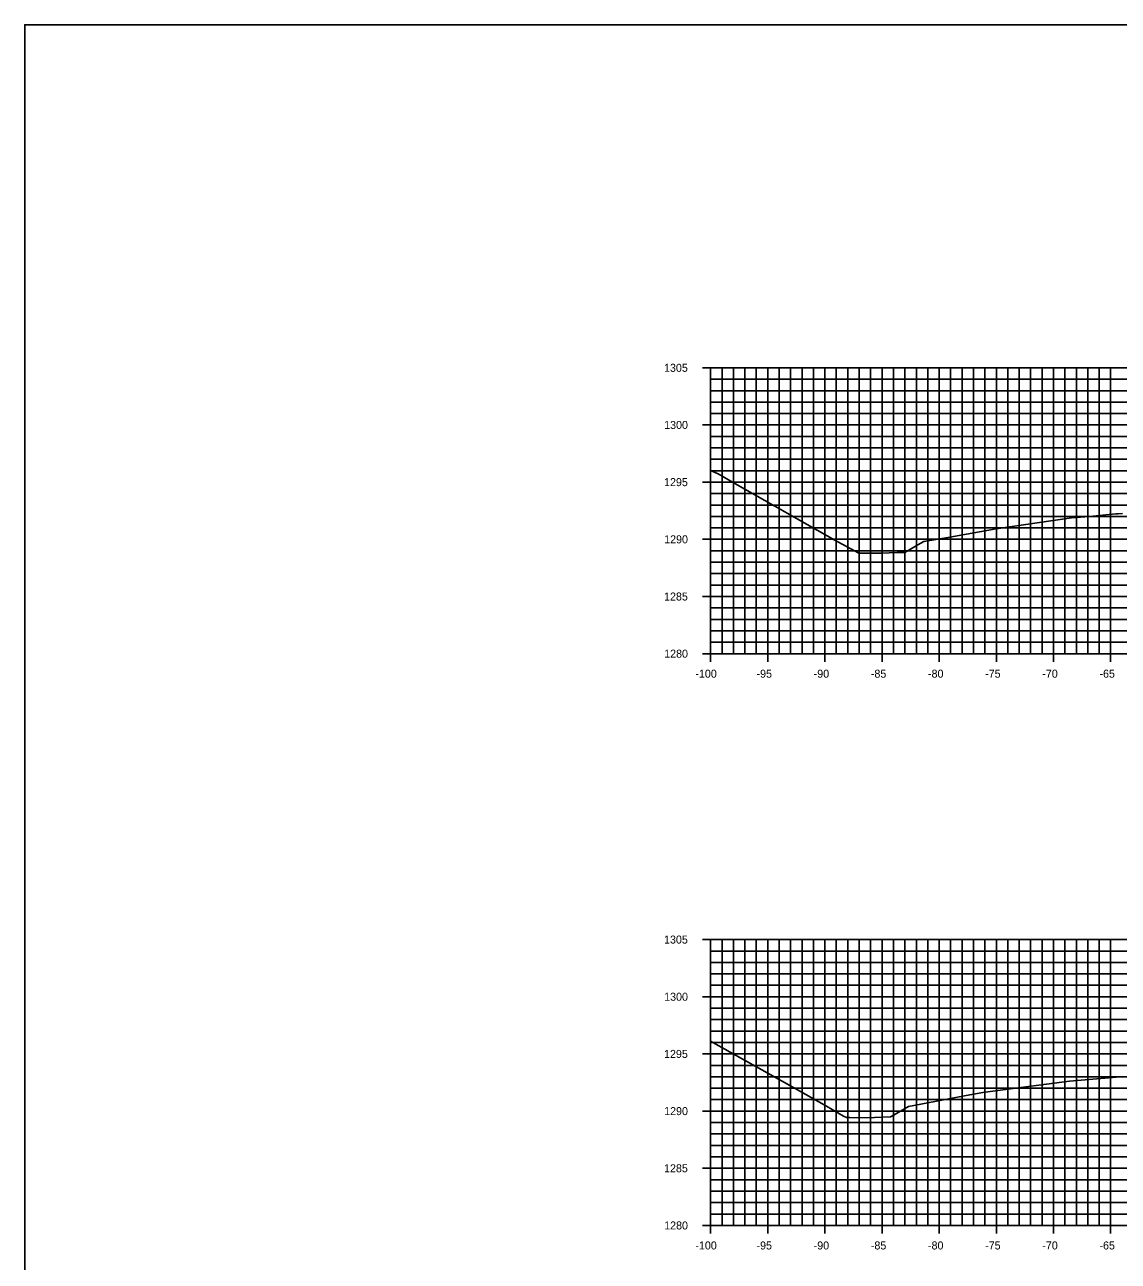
# Model space of a CAD drawing. Extents: x 674939 to 678919, y 750652 to 765176.
# Drawn here: x 678578.5 to 678674.2, y 754944.4 to 755052.6 of the extents above; entities that cross this region are included whole.
import ezdxf

# ---------------------------------------------------------------- set-up
doc = ezdxf.new("R2010")
doc.units = 0
for name, color, linetype in [('R_Axis', 7, 'Continuous'), ('R_Axis Annot', 7, 'Continuous'), ('R_Exist Surface', 7, 'Continuous'), ('R_Grid', 7, 'Continuous'), ('R_No Plot', 7, 'Continuous')]:
    doc.layers.add(name, color=color, linetype=linetype)

msp = doc.modelspace()

# ---------------------------------------------------------------- linework, layer by layer
at = {"layer": 'R_Axis'}
for p, q in [((678637.83, 755022.55), (678639.23, 755022.55)), ((678638.53, 754997.55), (678638.53, 755022.55)), ((678638.53, 755021.55), (678638.88, 755021.55)), ((678638.53, 755020.55), (678638.88, 755020.55)), ((678638.53, 755019.55), (678638.88, 755019.55)), ((678638.53, 755018.55), (678638.88, 755018.55)), ((678637.83, 755017.55), (678639.23, 755017.55)), ((678638.53, 755016.55), (678638.88, 755016.55)), ((678638.53, 755015.55), (678638.88, 755015.55)), ((678638.53, 755014.55), (678638.88, 755014.55)), ((678638.53, 755013.55), (678638.88, 755013.55)), ((678637.83, 755012.55), (678639.23, 755012.55)), ((678638.53, 755011.55), (678638.88, 755011.55)), ((678638.53, 755010.55), (678638.88, 755010.55)), ((678638.53, 755009.55), (678638.88, 755009.55)), ((678638.53, 755008.55), (678638.88, 755008.55)), ((678637.83, 755007.55), (678639.23, 755007.55)), ((678638.53, 755006.55), (678638.88, 755006.55)), ((678638.53, 755005.55), (678638.88, 755005.55)), ((678638.53, 755004.55), (678638.88, 755004.55)), ((678638.53, 755003.55), (678638.88, 755003.55)), ((678637.83, 755002.55), (678639.23, 755002.55)), ((678638.53, 755001.55), (678638.88, 755001.55)), ((678638.53, 755000.55), (678638.88, 755000.55)), ((678638.53, 754999.55), (678638.88, 754999.55)), ((678638.53, 754998.55), (678638.88, 754998.55)), ((678638.53, 754996.85), (678638.53, 754998.25)), ((678643.53, 754996.85), (678643.53, 754998.25)), ((678648.53, 754996.85), (678648.53, 754998.25)), ((678653.53, 754996.85), (678653.53, 754998.25)), ((678658.53, 754996.85), (678658.53, 754998.25)), ((678663.53, 754996.85), (678663.53, 754998.25)), ((678668.53, 754996.85), (678668.53, 754998.25)), ((678673.53, 754996.85), (678673.53, 754998.25)), ((678637.83, 754997.55), (678639.23, 754997.55)), ((678638.53, 754997.55), (678838.53, 754997.55)), ((678637.83, 754972.55), (678639.23, 754972.55)), ((678638.53, 754947.55), (678638.53, 754972.55)), ((678638.53, 754971.55), (678638.88, 754971.55)), ((678638.53, 754970.55), (678638.88, 754970.55)), ((678638.53, 754969.55), (678638.88, 754969.55)), ((678638.53, 754968.55), (678638.88, 754968.55)), ((678637.83, 754967.55), (678639.23, 754967.55)), ((678638.53, 754966.55), (678638.88, 754966.55)), ((678638.53, 754965.55), (678638.88, 754965.55)), ((678638.53, 754964.55), (678638.88, 754964.55)), ((678638.53, 754963.55), (678638.88, 754963.55)), ((678637.83, 754962.55), (678639.23, 754962.55)), ((678638.53, 754961.55), (678638.88, 754961.55)), ((678638.53, 754960.55), (678638.88, 754960.55)), ((678638.53, 754959.55), (678638.88, 754959.55)), ((678638.53, 754958.55), (678638.88, 754958.55)), ((678637.83, 754957.55), (678639.23, 754957.55)), ((678638.53, 754956.55), (678638.88, 754956.55)), ((678638.53, 754955.55), (678638.88, 754955.55)), ((678638.53, 754954.55), (678638.88, 754954.55)), ((678638.53, 754953.55), (678638.88, 754953.55)), ((678637.83, 754952.55), (678639.23, 754952.55)), ((678638.53, 754951.55), (678638.88, 754951.55)), ((678638.53, 754950.55), (678638.88, 754950.55)), ((678638.53, 754949.55), (678638.88, 754949.55)), ((678638.53, 754948.55), (678638.88, 754948.55)), ((678638.53, 754946.85), (678638.53, 754948.25)), ((678643.53, 754946.85), (678643.53, 754948.25)), ((678648.53, 754946.85), (678648.53, 754948.25)), ((678653.53, 754946.85), (678653.53, 754948.25)), ((678658.53, 754946.85), (678658.53, 754948.25)), ((678663.53, 754946.85), (678663.53, 754948.25)), ((678668.53, 754946.85), (678668.53, 754948.25)), ((678673.53, 754946.85), (678673.53, 754948.25)), ((678637.83, 754947.55), (678639.23, 754947.55)), ((678638.53, 754947.55), (678838.53, 754947.55))]:
    msp.add_line(p, q, dxfattribs=at)
at = {"layer": 'R_Exist Surface'}
for points in [[(678638.53, 755013.57), (678639.19, 755013.28), (678640.66, 755012.44), (678649.6, 755007.37), (678650.11, 755007.09), (678651.5, 755006.35), (678652.11, 755006.35), (678653.46, 755006.34), (678654.84, 755006.39), (678655.51, 755006.41), (678656.65, 755007.06), (678657.19, 755007.37), (678659.45, 755007.75), (678663.5, 755008.46), (678667.11, 755008.99), (678670.1, 755009.42), (678671.67, 755009.56), (678673.97, 755009.77), (678674.05, 755009.77), (678674.18, 755009.77), (678674.57, 755009.8)], [(678638.53, 754963.66), (678645.72, 754959.64), (678648.67, 754957.98), (678650.16, 754957.12), (678650.41, 754956.98), (678650.72, 754956.98), (678652.54, 754956.96), (678652.87, 754956.98), (678654.28, 754957.04), (678654.6, 754957.22), (678655.85, 754957.95), (678661.21, 754958.96), (678662.36, 754959.18), (678663.66, 754959.35), (678669.93, 754960.17), (678673.69, 754960.5), (678674.01, 754960.53), (678674.01, 754960.53), (678675.52, 754960.61)]]:
    msp.add_lwpolyline(points, dxfattribs=at)
at = {"layer": 'R_Grid'}
for p, q in [((678638.53, 755022.55), (678838.53, 755022.55)), ((678638.53, 754997.55), (678638.53, 755022.55)), ((678639.53, 754997.55), (678639.53, 755022.55)), ((678640.53, 754997.55), (678640.53, 755022.55)), ((678641.53, 754997.55), (678641.53, 755022.55)), ((678642.53, 754997.55), (678642.53, 755022.55)), ((678643.53, 754997.55), (678643.53, 755022.55)), ((678644.53, 754997.55), (678644.53, 755022.55)), ((678645.53, 754997.55), (678645.53, 755022.55)), ((678646.53, 754997.55), (678646.53, 755022.55)), ((678647.53, 754997.55), (678647.53, 755022.55)), ((678648.53, 754997.55), (678648.53, 755022.55)), ((678649.53, 754997.55), (678649.53, 755022.55)), ((678650.53, 754997.55), (678650.53, 755022.55)), ((678651.53, 754997.55), (678651.53, 755022.55)), ((678652.53, 754997.55), (678652.53, 755022.55)), ((678653.53, 754997.55), (678653.53, 755022.55)), ((678654.53, 754997.55), (678654.53, 755022.55)), ((678655.53, 754997.55), (678655.53, 755022.55)), ((678656.53, 754997.55), (678656.53, 755022.55)), ((678657.53, 754997.55), (678657.53, 755022.55)), ((678658.53, 754997.55), (678658.53, 755022.55)), ((678659.53, 754997.55), (678659.53, 755022.55)), ((678660.53, 754997.55), (678660.53, 755022.55)), ((678661.53, 754997.55), (678661.53, 755022.55)), ((678662.53, 754997.55), (678662.53, 755022.55)), ((678663.53, 754997.55), (678663.53, 755022.55)), ((678664.53, 754997.55), (678664.53, 755022.55)), ((678665.53, 754997.55), (678665.53, 755022.55)), ((678666.53, 754997.55), (678666.53, 755022.55)), ((678667.53, 754997.55), (678667.53, 755022.55)), ((678668.53, 754997.55), (678668.53, 755022.55)), ((678669.53, 754997.55), (678669.53, 755022.55)), ((678670.53, 754997.55), (678670.53, 755022.55)), ((678671.53, 754997.55), (678671.53, 755022.55)), ((678672.53, 754997.55), (678672.53, 755022.55)), ((678673.53, 754997.55), (678673.53, 755022.55)), ((678638.53, 755021.55), (678838.53, 755021.55)), ((678638.53, 755020.55), (678838.53, 755020.55)), ((678638.53, 755019.55), (678838.53, 755019.55)), ((678638.53, 755018.55), (678838.53, 755018.55)), ((678638.53, 755017.55), (678838.53, 755017.55)), ((678638.53, 755016.55), (678838.53, 755016.55)), ((678638.53, 755015.55), (678838.53, 755015.55)), ((678638.53, 755014.55), (678838.53, 755014.55)), ((678638.53, 755013.55), (678838.53, 755013.55)), ((678638.53, 755012.55), (678838.53, 755012.55)), ((678638.53, 755011.55), (678838.53, 755011.55)), ((678638.53, 755010.55), (678838.53, 755010.55)), ((678638.53, 755009.55), (678838.53, 755009.55)), ((678638.53, 755008.55), (678838.53, 755008.55)), ((678638.53, 755007.55), (678838.53, 755007.55)), ((678638.53, 755006.55), (678838.53, 755006.55)), ((678638.53, 755005.55), (678838.53, 755005.55)), ((678638.53, 755004.55), (678838.53, 755004.55)), ((678638.53, 755003.55), (678838.53, 755003.55)), ((678638.53, 755002.55), (678838.53, 755002.55)), ((678638.53, 755001.55), (678838.53, 755001.55)), ((678638.53, 755000.55), (678838.53, 755000.55)), ((678638.53, 754999.55), (678838.53, 754999.55)), ((678638.53, 754998.55), (678838.53, 754998.55)), ((678638.53, 754997.55), (678838.53, 754997.55)), ((678638.53, 754972.55), (678838.53, 754972.55)), ((678638.53, 754947.55), (678638.53, 754972.55)), ((678639.53, 754947.55), (678639.53, 754972.55)), ((678640.53, 754947.55), (678640.53, 754972.55)), ((678641.53, 754947.55), (678641.53, 754972.55)), ((678642.53, 754947.55), (678642.53, 754972.55)), ((678643.53, 754947.55), (678643.53, 754972.55)), ((678644.53, 754947.55), (678644.53, 754972.55)), ((678645.53, 754947.55), (678645.53, 754972.55)), ((678646.53, 754947.55), (678646.53, 754972.55)), ((678647.53, 754947.55), (678647.53, 754972.55)), ((678648.53, 754947.55), (678648.53, 754972.55)), ((678649.53, 754947.55), (678649.53, 754972.55)), ((678650.53, 754947.55), (678650.53, 754972.55)), ((678651.53, 754947.55), (678651.53, 754972.55)), ((678652.53, 754947.55), (678652.53, 754972.55)), ((678653.53, 754947.55), (678653.53, 754972.55)), ((678654.53, 754947.55), (678654.53, 754972.55)), ((678655.53, 754947.55), (678655.53, 754972.55)), ((678656.53, 754947.55), (678656.53, 754972.55)), ((678657.53, 754947.55), (678657.53, 754972.55)), ((678658.53, 754947.55), (678658.53, 754972.55)), ((678659.53, 754947.55), (678659.53, 754972.55)), ((678660.53, 754947.55), (678660.53, 754972.55)), ((678661.53, 754947.55), (678661.53, 754972.55)), ((678662.53, 754947.55), (678662.53, 754972.55)), ((678663.53, 754947.55), (678663.53, 754972.55)), ((678664.53, 754947.55), (678664.53, 754972.55)), ((678665.53, 754947.55), (678665.53, 754972.55)), ((678666.53, 754947.55), (678666.53, 754972.55)), ((678667.53, 754947.55), (678667.53, 754972.55)), ((678668.53, 754947.55), (678668.53, 754972.55)), ((678669.53, 754947.55), (678669.53, 754972.55)), ((678670.53, 754947.55), (678670.53, 754972.55)), ((678671.53, 754947.55), (678671.53, 754972.55)), ((678672.53, 754947.55), (678672.53, 754972.55)), ((678673.53, 754947.55), (678673.53, 754972.55)), ((678638.53, 754971.55), (678838.53, 754971.55)), ((678638.53, 754970.55), (678838.53, 754970.55)), ((678638.53, 754969.55), (678838.53, 754969.55)), ((678638.53, 754968.55), (678838.53, 754968.55)), ((678638.53, 754967.55), (678838.53, 754967.55)), ((678638.53, 754966.55), (678838.53, 754966.55)), ((678638.53, 754965.55), (678838.53, 754965.55)), ((678638.53, 754964.55), (678838.53, 754964.55)), ((678638.53, 754963.55), (678838.53, 754963.55)), ((678638.53, 754962.55), (678838.53, 754962.55)), ((678638.53, 754961.55), (678838.53, 754961.55)), ((678638.53, 754960.55), (678838.53, 754960.55)), ((678638.53, 754959.55), (678838.53, 754959.55)), ((678638.53, 754958.55), (678838.53, 754958.55)), ((678638.53, 754957.55), (678838.53, 754957.55)), ((678638.53, 754956.55), (678838.53, 754956.55)), ((678638.53, 754955.55), (678838.53, 754955.55)), ((678638.53, 754954.55), (678838.53, 754954.55)), ((678638.53, 754953.55), (678838.53, 754953.55)), ((678638.53, 754952.55), (678838.53, 754952.55)), ((678638.53, 754951.55), (678838.53, 754951.55)), ((678638.53, 754950.55), (678838.53, 754950.55)), ((678638.53, 754949.55), (678838.53, 754949.55)), ((678638.53, 754948.55), (678838.53, 754948.55)), ((678638.53, 754947.55), (678838.53, 754947.55))]:
    msp.add_line(p, q, dxfattribs=at)
at = {"layer": 'R_No Plot'}
msp.add_lwpolyline([(678578.53, 754832.55), (678918.53, 754832.55), (678918.53, 755052.55), (678578.53, 755052.55)], close=True, dxfattribs=at)

# ---------------------------------------------------------------- texts
at = {"layer": 'R_Axis Annot'}
for s, p in [('1305', (678634.46, 755022.2)), ('1300', (678634.47, 755017.2)), ('1295', (678634.46, 755012.2)), ('1290', (678634.47, 755007.2)), ('1285', (678634.46, 755002.2)), ('1280', (678634.47, 754997.2)), ('-100', (678637.2, 754995.45)), ('-95', (678642.55, 754995.45)), ('-90', (678647.55, 754995.45)), ('-85', (678652.55, 754995.45)), ('-80', (678657.55, 754995.45)), ('-75', (678662.55, 754995.45)), ('-70', (678667.55, 754995.45)), ('-65', (678672.55, 754995.45)), ('1305', (678634.46, 754972.2)), ('1300', (678634.47, 754967.2)), ('1295', (678634.46, 754962.2)), ('1290', (678634.47, 754957.2)), ('1285', (678634.46, 754952.2)), ('1280', (678634.47, 754947.2)), ('-100', (678637.2, 754945.45)), ('-95', (678642.55, 754945.45)), ('-90', (678647.55, 754945.45)), ('-85', (678652.55, 754945.45)), ('-80', (678657.55, 754945.45)), ('-75', (678662.55, 754945.45)), ('-70', (678667.55, 754945.45)), ('-65', (678672.55, 754945.45))]:
    msp.add_text(s, height=0.7, dxfattribs=at).set_placement(p)

doc.saveas('drawing.dxf')
